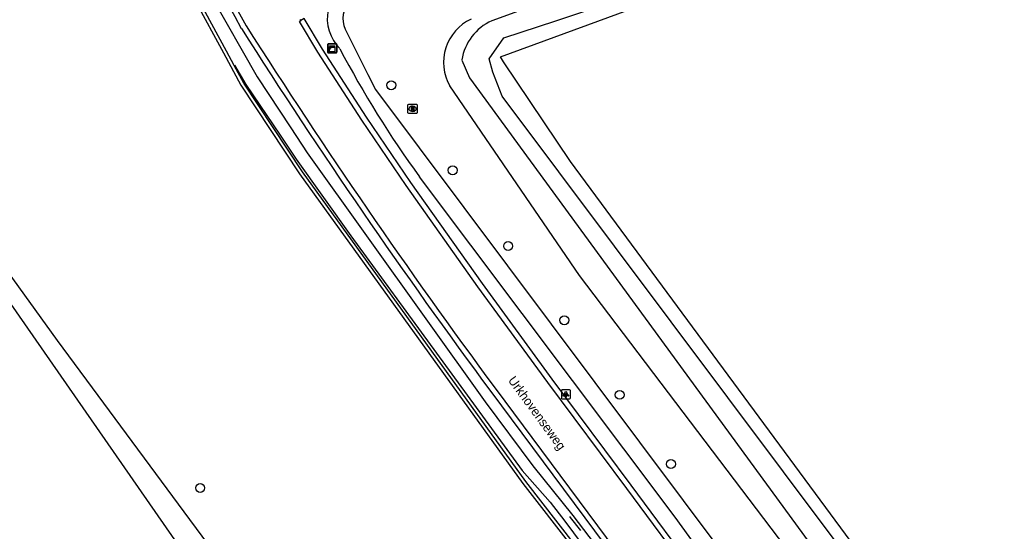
# Model space of a CAD drawing. Extents: x 164494 to 166241, y 382475 to 384494.
# Drawn here: x 164815.9 to 164923.4, y 383393 to 383449 of the extents above; entities that cross this region are included whole.
import ezdxf

# ---------------------------------------------------------------- set-up
doc = ezdxf.new("R2010")
doc.units = 0
for name, color, linetype in [('IMGEO_Berm_halfverhard', 7, 'Continuous'), ('IMGEO_Boom', 7, 'Continuous'), ('IMGEO_Bouwland', 7, 'Continuous'), ('IMGEO_Duiker', 7, 'Continuous'), ('IMGEO_Grasland_overig', 7, 'Continuous'), ('IMGEO_Haag', 7, 'Continuous'), ('IMGEO_Kast', 7, 'Continuous'), ('IMGEO_Lichtpunt', 7, 'Continuous'), ('IMGEO_Openbare_ruimte_label', 7, 'Continuous'), ('IMGEO_Rijbaan_lokaal_gesloten', 7, 'Continuous'), ('IMGEO_Rioolput', 7, 'Continuous'), ('IMGEO_Waterloop', 7, 'Continuous')]:
    doc.layers.add(name, color=color, linetype=linetype)

msp = doc.modelspace()

# ---------------------------------------------------------------- linework, layer by layer
at = {"layer": 'IMGEO_Berm_halfverhard'}
for points in [[(164917.66, 383351.27), (164910.61, 383360.67), (164905.47, 383367.54), (164899.5, 383375.58), (164890.32, 383388.04), (164882.91, 383398.06), (164874.24, 383409.65), (164866.6, 383420.14), (164858.74, 383431.2), (164853.9, 383438.37), (164849.08, 383445.81), (164847.08, 383449.16), (164846.7, 383448.94)], [(164867.51, 383408.32), (164897.15, 383368.52)]]:
    msp.add_lwpolyline(points, dxfattribs=at)
for centre, radius, start, end in [((165193.75, 383642.59), 403.55, 202.0084, 208.8174), ((165413.22, 383812.71), 679.21, 212.46919, 216.54003)]:
    msp.add_arc(centre, radius, start, end, dxfattribs=at)
at = {"layer": 'IMGEO_Boom'}
for centre in [(164856.61, 383441.86), (164863.34, 383432.54), (164869.42, 383424.25), (164875.58, 383416.12), (164881.65, 383407.95), (164887.26, 383400.37), (164835.67, 383397.75)]:
    msp.add_circle(centre, 0.489, dxfattribs=at)
at = {"layer": 'IMGEO_Bouwland'}
msp.add_lwpolyline([(164912.57, 383384.32), (164876.26, 383433.49), (164868.93, 383444.42), (164868.58, 383444.96), (164910.85, 383460.5), (164926.47, 383465.46), (164933.68, 383466.56), (164938.58, 383467.93), (164939.06, 383467.99)], dxfattribs=at)
at = {"layer": 'IMGEO_Duiker'}
msp.add_lwpolyline([(164877.37, 383393.08), (164876.24, 383394.53), (164876.17, 383394.62)], dxfattribs=at)
at = {"layer": 'IMGEO_Grasland_overig'}
for points in [[(164867.48, 383349.75), (164820.04, 383413.91), (164785.33, 383462.01), (164783.79, 383461)], [(164783.79, 383461), (164814.94, 383417.89), (164860.76, 383351.9)], [(164863.01, 383441.79), (164877.21, 383421.03), (164908.78, 383379.42), (164910.2, 383379.26), (164913, 383381.45), (164913.11, 383382.53), (164912.57, 383384.32)]]:
    msp.add_lwpolyline(points, dxfattribs=at)
msp.add_arc((164867.62, 383444.35), 5.27, 115.4958, 209.0546, dxfattribs=at)
at = {"layer": 'IMGEO_Haag'}
for points in [[(164818.1, 383474.42), (164820.22, 383475.23), (164821.99, 383475.91), (164825.55, 383468.75), (164832, 383456.85), (164838.21, 383445.41), (164840.13, 383441.87), (164846.57, 383432.14), (164871.03, 383398.23), (164886.94, 383377.76), (164867.48, 383349.75)], [(164867.74, 383349.42), (164887.44, 383377.77), (164871.35, 383398.47), (164846.9, 383432.37), (164840.47, 383442.08), (164839.41, 383444.04)]]:
    msp.add_lwpolyline(points, dxfattribs=at)
at = {"layer": 'IMGEO_Kast'}
for p, q in [((164849.65, 383445.48), (164849.65, 383446.32)), ((164849.65, 383446.32), (164849.65, 383445.48)), ((164849.72, 383446.4), (164850.56, 383446.4)), ((164850.56, 383446.4), (164849.72, 383446.4)), ((164850.64, 383446.33), (164850.64, 383445.49)), ((164850.64, 383445.49), (164850.64, 383446.33)), ((164850.57, 383445.4), (164849.73, 383445.4)), ((164849.73, 383445.4), (164850.57, 383445.4))]:
    msp.add_line(p, q, dxfattribs=at)
for points in [[(164849.84, 383446.19), (164850.44, 383446.19), (164850.44, 383446.11), (164849.84, 383446.11), (164849.84, 383446.19)], [(164849.84, 383446.02), (164850.44, 383446.02), (164850.44, 383445.53), (164849.84, 383445.53), (164849.84, 383446.02)]]:
    msp.add_lwpolyline(points, dxfattribs=at)
msp.add_circle((164849.92, 383445.86), 0.0377, dxfattribs=at)
for centre, start, end in [((164849.72, 383446.32), 92.4484, 184.2845), ((164849.72, 383446.32), 92.4484, 184.2845), ((164850.57, 383446.32), 2.4484, 94.2845), ((164850.57, 383446.32), 2.4484, 94.2845), ((164849.72, 383445.48), 182.4484, 274.2845), ((164849.72, 383445.48), 182.4484, 274.2845), ((164850.57, 383445.48), 272.4484, 4.2845), ((164850.57, 383445.48), 272.4484, 4.2845)]:
    msp.add_arc(centre, 0.0779, start, end, dxfattribs=at)
at = {"layer": 'IMGEO_Lichtpunt'}
for p, q in [((164875.25, 383408.41), (164875.25, 383407.61)), ((164875.25, 383408.41), (164875.25, 383407.61)), ((164876.15, 383408.51), (164875.34, 383408.51)), ((164876.15, 383408.51), (164875.34, 383408.51)), ((164875.34, 383407.51), (164876.15, 383407.51)), ((164875.34, 383407.51), (164876.15, 383407.51)), ((164876.24, 383407.61), (164876.24, 383408.41)), ((164876.24, 383407.61), (164876.24, 383408.41))]:
    msp.add_line(p, q, dxfattribs=at)
for points in [[(164875.62, 383408.08), (164875.66, 383408.05), (164875.47, 383407.79), (164875.43, 383407.82), (164875.62, 383408.08)], [(164875.72, 383408.03), (164875.77, 383408.03), (164875.77, 383407.71), (164875.72, 383407.71), (164875.72, 383408.03)], [(164875.83, 383408.05), (164875.87, 383408.08), (164876.06, 383407.81), (164876.02, 383407.79), (164875.83, 383408.05)]]:
    msp.add_lwpolyline(points, dxfattribs=at)
msp.add_circle((164875.75, 383408.21), 0.0994, dxfattribs=at)
for centre, start, end in [((164875.34, 383408.41), 90, 180), ((164875.34, 383408.41), 90, 180), ((164875.34, 383407.61), 180, 270), ((164875.34, 383407.61), 180, 270), ((164876.15, 383408.41), 0, 90), ((164876.15, 383408.41), 0, 90), ((164876.15, 383407.61), 270, 0), ((164876.15, 383407.61), 270, 360)]:
    msp.add_arc(centre, 0.0946, start, end, dxfattribs=at)
at = {"layer": 'IMGEO_Rijbaan_lokaal_gesloten'}
for points in [[(164917.27, 383350.99), (164917.17, 383350.92), (164910.13, 383360.31), (164904.99, 383367.18), (164899.02, 383375.23), (164889.83, 383387.69), (164882.43, 383397.7), (164873.76, 383409.3), (164866.11, 383419.79), (164858.24, 383430.87), (164853.39, 383438.04), (164848.57, 383445.5), (164846.56, 383448.85), (164846.7, 383448.94)], [(164846.7, 383448.94), (164846.63, 383449.05)], [(164867.99, 383408.67), (164897.53, 383369.01), (164899.31, 383366.62), (164947.02, 383302.56)]]:
    msp.add_lwpolyline(points, dxfattribs=at)
for centre, radius, start, end in [((165203.85, 383647.76), 414.29, 202.1514, 208.7706), ((165414.74, 383813.77), 680.46, 212.47903, 216.53556)]:
    msp.add_arc(centre, radius, start, end, dxfattribs=at)
at = {"layer": 'IMGEO_Rioolput'}
for p, q in [((164858.44, 383438.85), (164858.44, 383439.71)), ((164858.52, 383439.78), (164859.37, 383439.78)), ((164859.44, 383439.71), (164859.44, 383438.85)), ((164859.37, 383438.78), (164858.52, 383438.78)), ((164858.93, 383439.56), (164858.95, 383439.56)), ((164858.95, 383439), (164858.93, 383439))]:
    msp.add_line(p, q, dxfattribs=at)
for points in [[(164858.44, 383438.85), (164858.44, 383439.71)], [(164858.52, 383439.78), (164859.37, 383439.78)], [(164859.44, 383439.71), (164859.44, 383438.85)], [(164859.37, 383438.78), (164858.52, 383438.78)], [(164859.03, 383439.48), (164858.78, 383439.48), (164858.78, 383439.08)], [(164858.78, 383439.08), (164858.9, 383439.08), (164858.9, 383439.24), (164858.91, 383439.24)], [(164858.96, 383439.4), (164858.9, 383439.4), (164858.9, 383439.32)], [(164858.9, 383439.32), (164858.95, 383439.32)], [(164858.96, 383439.21), (164859.03, 383439.08), (164859.17, 383439.08), (164859.11, 383439.21)]]:
    msp.add_lwpolyline(points, dxfattribs=at)
for centre, radius, start, end in [((164858.52, 383439.7), 0.0765, 91.552, 178.448), ((164858.52, 383439.7), 0.0765, 91.552, 178.448), ((164859.37, 383439.7), 0.0765, 1.552, 88.448), ((164859.37, 383439.7), 0.0765, 1.552, 88.448), ((164858.52, 383438.85), 0.0765, 181.552, 268.448), ((164858.52, 383438.85), 0.0765, 181.552, 268.448), ((164858.91, 383439.19), 0.0533, 26.0293, 88.6989), ((164858.94, 383439.51), 0.19, 274.7715, 282.9687), ((164858.96, 383439.3), 0.0964, 77.0061, 93.1865), ((164858.98, 383439.36), 0.0378, 276.6634, 79.6772), ((164859.03, 383439.37), 0.109, 350.3612, 89.416), ((164859.03, 383439.37), 0.112, 277.5842, 350.9817), ((164859.01, 383439.15), 0.108, 29.5134, 73.7905), ((164859.37, 383438.85), 0.0765, 271.552, 358.448), ((164859.37, 383438.85), 0.0765, 271.552, 358.448)]:
    msp.add_arc(centre, radius, start, end, dxfattribs=at)
for centre, major_axis, ratio, start_param, end_param in [((164858.93, 383439.28), (-0.387, 0.002), 0.722429, 4.712389, 7.853982), ((164858.95, 383439.28), (-0.39, 0.002), 0.717154, 1.570796, 4.712389)]:
    msp.add_ellipse(centre, major_axis=major_axis, ratio=ratio, start_param=start_param, end_param=end_param, dxfattribs=at)
at = {"layer": 'IMGEO_Waterloop'}
for points in [[(164831.93, 383457.82), (164831.98, 383457.84), (164830.93, 383460.2), (164823.39, 383474.16), (164822.27, 383476.85), (164822.96, 383478.06), (164827.35, 383469.44), (164831.32, 383462.78), (164831.86, 383461.66), (164836.83, 383451.72), (164841.91, 383442.78), (164845.59, 383437.2), (164847.39, 383434.46), (164866.92, 383407.17), (164872.11, 383400.17), (164876.52, 383394.73), (164895.26, 383370.16)], [(164936.43, 383470.39), (164935.09, 383470.66), (164932.28, 383470.84), (164928.21, 383470.57), (164925.96, 383469.94), (164913.96, 383465.77), (164867.62, 383448.92)], [(164910.33, 383380.92), (164911.91, 383382.14), (164905.8, 383391.22), (164868.77, 383440.66), (164867.75, 383443.3), (164867.33, 383444.75), (164868.94, 383447.05), (164874.65, 383448.92), (164925.99, 383466.08), (164931.25, 383467.09), (164934.71, 383467.81), (164936.3, 383468.22)], [(164839.41, 383444.04), (164838.56, 383445.6), (164832.36, 383457.04), (164831.93, 383457.82)], [(164851.56, 383448), (164854.05, 383443.05), (164854.9, 383441.38), (164907.84, 383370.66), (164907.93, 383370.56)], [(164839.41, 383444.04), (164839.45, 383444.06), (164840.67, 383441.95), (164844.42, 383436.39), (164846.18, 383433.78), (164852.18, 383425.35), (164870.97, 383399.68), (164874.04, 383396.21), (164875.65, 383394.11), (164888.28, 383377.09)], [(164864.35, 383444.62), (164865.2, 383442.66), (164910.33, 383380.92)], [(164907.93, 383370.56), (164906.45, 383369.42), (164898.56, 383379.57), (164887.73, 383394.54), (164859.72, 383431.84)]]:
    msp.add_lwpolyline(points, dxfattribs=at)
for centre, radius, start, end in [((164854.28, 383449.2), 4.68, 112.2694, 225.4099), ((164854.03, 383449.14), 2.72, 135.1227, 204.8315), ((164869.97, 383443.74), 5.69, 114.3312, 171.0384), ((164946.92, 383495.86), 108.18, 207.5258, 216.2857)]:
    msp.add_arc(centre, radius, start, end, dxfattribs=at)

# ---------------------------------------------------------------- texts
at = {"layer": 'IMGEO_Openbare_ruimte_label'}
msp.add_text('Urkhovenseweg', height=1, rotation=306.1706, dxfattribs=at).set_placement((164869.36, 383409.53))

doc.saveas('drawing.dxf')
